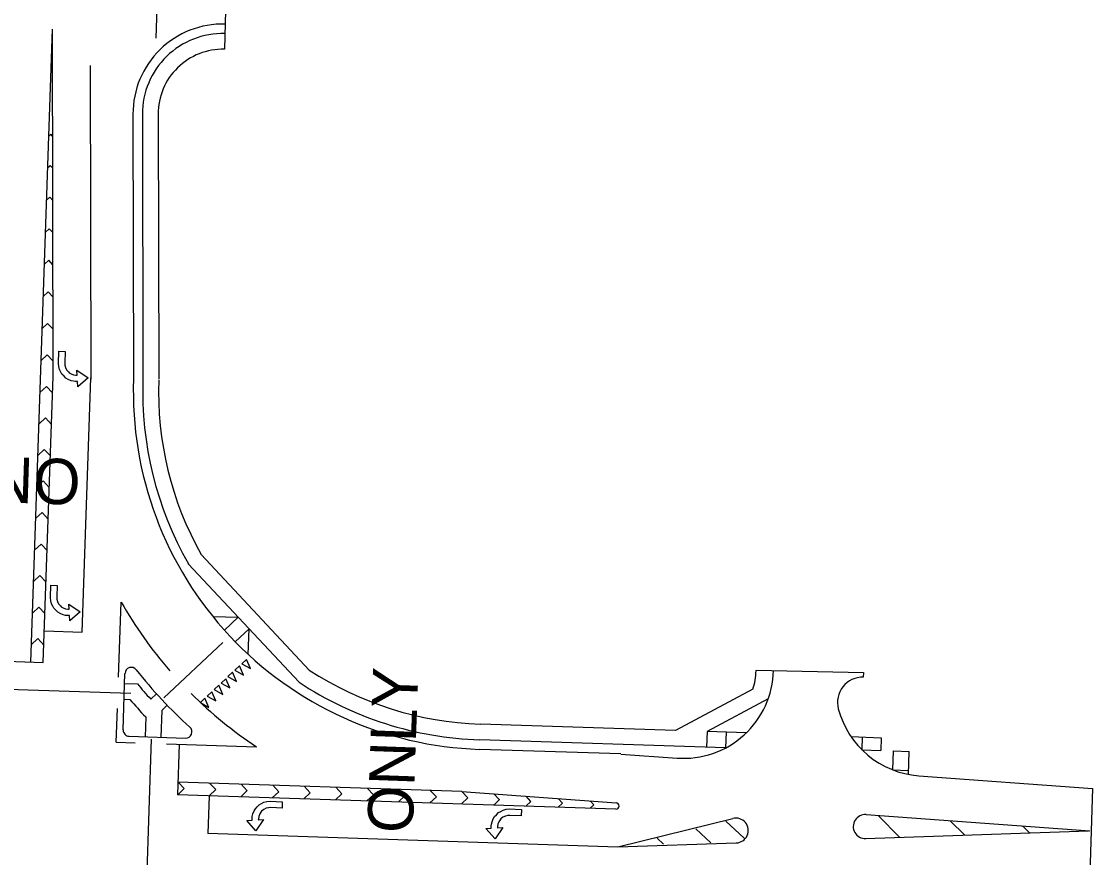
# Model space of a CAD drawing. Extents: x 979036 to 996074, y 1836928 to 1845163.
# Drawn here: x 992489.6 to 992829.2, y 1843370.6 to 1843635.7 of the extents above; entities that cross this region are included whole.
import ezdxf

# ---------------------------------------------------------------- set-up
doc = ezdxf.new("R2010")
doc.units = 0
for name, color, linetype in [('R_Proposed Road', 7, 'Continuous'), ('STRIPE_White Crosswalk', 7, 'Continuous'), ('STRIPE_White Stopbar', 7, 'Continuous'), ('STRIPE_White Turn Arrow', 7, 'Continuous'), ('STRIPE_White_6in', 7, 'Continuous'), ('STRIPE_White_ONLY', 7, 'Continuous'), ('STRIPE_White_Yield Tri', 7, 'Continuous'), ('STRIPE_Yellow Dbl 6in', 7, 'Continuous'), ('STRIPE_Yellow_45_Diag_8in', 7, 'Continuous')]:
    doc.layers.add(name, color=color, linetype=linetype)

msp = doc.modelspace()

# ---------------------------------------------------------------- linework, layer by layer
at = {"layer": 'R_Proposed Road'}
for p, q in [((992554.9, 1843665.68), (992553.93, 1843626.83)), ((992524.91, 1843606.28), (992525.09, 1843522.27)), ((992527.91, 1843606.29), (992528.09, 1843522.28)), ((992532.91, 1843606.3), (992533.09, 1843522.29)), ((992546.53, 1843466.67), (992580.81, 1843430.01)), ((992542.47, 1843463.69), (992577.56, 1843426.16)), ((992550.21, 1843447.02), (992558.31, 1843446.75)), ((992558.31, 1843446.75), (992553.93, 1843442.65)), ((992561.73, 1843443.1), (992557.34, 1843439)), ((992561.46, 1843435), (992561.73, 1843443.1)), ((992521.78, 1843411.1), (992522.39, 1843428.96)), ((992722.48, 1843430.02), (992722.47, 1843429.84)), ((992722.47, 1843430.02), (992756.51, 1843429.25)), ((992756.51, 1843429.25), (992756.47, 1843427.76)), ((992522.28, 1843425.76), (992526.33, 1843425.62)), ((992721.45, 1843423.94), (992696.95, 1843410.85)), ((992522.11, 1843420.77), (992523.95, 1843420.7)), ((992532.38, 1843422.5), (992530.54, 1843420.79)), ((992726.3, 1843420.86), (992706.95, 1843410.52)), ((992534.02, 1843417.19), (992533.74, 1843408.71)), ((992535.79, 1843418.85), (992534.02, 1843417.19)), ((992528.95, 1843415.15), (992528.75, 1843408.87)), ((992696.95, 1843410.85), (992635.06, 1843412.88)), ((992706.95, 1843410.52), (992706.78, 1843405.53)), ((992719.36, 1843410.12), (992706.95, 1843410.52)), ((992712.94, 1843410.33), (992712.78, 1843405.33)), ((992523.71, 1843409.04), (992541.57, 1843408.45)), ((992712.78, 1843405.33), (992634.89, 1843407.89)), ((992752.55, 1843408.93), (992762.14, 1843408.54)), ((992756.15, 1843408.78), (992755.98, 1843404.79)), ((992762.14, 1843408.54), (992761.98, 1843404.54)), ((992679.57, 1843403.42), (992634.8, 1843404.89)), ((992679.63, 1843403.41), (992697.42, 1843402.12)), ((992755.98, 1843404.78), (992761.98, 1843404.54)), ((992765.81, 1843398.38), (992766.01, 1843404.38)), ((992766.01, 1843404.38), (992771, 1843404.21)), ((992770.76, 1843396.96), (992771, 1843404.21)), ((992765.81, 1843398.38), (992770.81, 1843398.22)), ((992774.05, 1843396.53), (992829.16, 1843392.5)), ((992829.16, 1843392.5), (992828.27, 1843365.51))]:
    msp.add_line(p, q, dxfattribs=at)
for centre, radius, start, end in [((992553.41, 1843606.34), 28.5, 88.5687, 180.1187), ((992553.41, 1843606.34), 25.5, 88.5687, 180.1187), ((992553.41, 1843606.34), 20.5, 88.5687, 180.1187), ((992638.52, 1843518.33), 113.5, 178.0361, 268.1194), ((992638.52, 1843518.33), 110.5, 178.0361, 209.6347), ((992638.52, 1843518.33), 105.5, 178.0361, 209.3184), ((992524.39, 1843428.89), 2, 38.0831, 178.0361), ((992638.52, 1843518.33), 143, 218.0831, 228.0725), ((992638.52, 1843518.33), 105.5, 236.8372, 268.1194), ((992699.49, 1843430.54), 28.5, 265.8268, 358.7075), ((992701.98, 1843430.36), 20.5, 341.7549, 358.5567), ((992756.29, 1843419.76), 8, 88.7075, 194.6721), ((992638.54, 1843519.03), 146, 219.7747, 222.2917), ((992638.52, 1843518.33), 110.5, 236.5208, 268.1194), ((992638.54, 1843519.03), 151, 220.6303, 223.4662), ((992776.12, 1843424.95), 28.5, 194.6721, 265.8268), ((992523.78, 1843411.03), 2, 178.0361, 268.1194), ((992541.63, 1843410.45), 2, 268.1194, 48.0725)]:
    msp.add_arc(centre, radius, start, end, dxfattribs=at)
at = {"layer": 'STRIPE_White Crosswalk'}
for p, q in [((992532.3, 1843630.35), (992533.5, 1843665.48)), ((992553.39, 1843438.72), (992534.7, 1843421.25)), ((992477.09, 1843424.27), (992524.25, 1843422.65)), ((992530.65, 1843408.15), (992529.03, 1843358.83))]:
    msp.add_line(p, q, dxfattribs=at)
at = {"layer": 'STRIPE_White Stopbar'}
for p, q in [((992496.84, 1843442.44), (992508.83, 1843442.03)), ((992480.01, 1843433.01), (992496.49, 1843432.45)), ((992539.6, 1843406.51), (992539.07, 1843390.51)), ((992549.07, 1843390.19), (992548.67, 1843378.2))]:
    msp.add_line(p, q, dxfattribs=at)
at = {"layer": 'STRIPE_White Turn Arrow'}
for points in [[(992507.11, 1843525.15), (992510.73, 1843522.71), (992507.45, 1843519.84), (992507.34, 1843521.5), (992506.68, 1843521.52), (992506.1, 1843521.57), (992505.31, 1843521.76), (992504.38, 1843522.16), (992503.66, 1843522.6), (992503.08, 1843523.16), (992502.41, 1843523.81), (992502.04, 1843524.51), (992501.63, 1843525.27), (992501.39, 1843526.22), (992501.27, 1843527.21), (992501.46, 1843531.11), (992503.46, 1843531.02), (992503.32, 1843527.42), (992503.35, 1843526.73), (992503.54, 1843525.99), (992503.89, 1843525.2), (992504.44, 1843524.54), (992504.74, 1843524.31), (992505.34, 1843523.92), (992506.1, 1843523.65), (992506.83, 1843523.51), (992507.22, 1843523.49)], [(992504.57, 1843450.95), (992508.18, 1843448.51), (992504.91, 1843445.63), (992504.8, 1843447.29), (992504.13, 1843447.31), (992503.56, 1843447.37), (992502.76, 1843447.56), (992501.84, 1843447.95), (992501.12, 1843448.39), (992500.54, 1843448.96), (992499.87, 1843449.61), (992499.49, 1843450.31), (992499.08, 1843451.07), (992498.85, 1843452.02), (992498.72, 1843453), (992498.91, 1843456.9), (992500.92, 1843456.81), (992500.78, 1843453.22), (992500.8, 1843452.53), (992501, 1843451.79), (992501.35, 1843450.99), (992501.9, 1843450.34), (992502.19, 1843450.11), (992502.8, 1843449.71), (992503.55, 1843449.44), (992504.28, 1843449.31), (992504.67, 1843449.28)], [(992566.32, 1843382.63), (992563.88, 1843379.01), (992561, 1843382.29), (992562.67, 1843382.4), (992562.68, 1843383.06), (992562.74, 1843383.64), (992562.93, 1843384.43), (992563.33, 1843385.36), (992563.76, 1843386.08), (992564.33, 1843386.66), (992564.98, 1843387.33), (992565.68, 1843387.7), (992566.44, 1843388.11), (992567.39, 1843388.35), (992568.38, 1843388.47), (992572.27, 1843388.28), (992572.18, 1843386.28), (992568.59, 1843386.42), (992567.9, 1843386.39), (992567.16, 1843386.2), (992566.37, 1843385.85), (992565.71, 1843385.3), (992565.48, 1843385), (992565.09, 1843384.4), (992564.82, 1843383.65), (992564.68, 1843382.91), (992564.66, 1843382.52)], [(992642.15, 1843380.16), (992639.71, 1843376.54), (992636.83, 1843379.82), (992638.49, 1843379.92), (992638.51, 1843380.59), (992638.57, 1843381.16), (992638.76, 1843381.96), (992639.15, 1843382.89), (992639.59, 1843383.61), (992640.16, 1843384.18), (992640.81, 1843384.86), (992641.51, 1843385.23), (992642.27, 1843385.64), (992643.22, 1843385.88), (992644.2, 1843386), (992648.1, 1843385.81), (992648.01, 1843383.81), (992644.42, 1843383.95), (992643.73, 1843383.92), (992642.99, 1843383.72), (992642.2, 1843383.37), (992641.54, 1843382.82), (992641.31, 1843382.53), (992640.91, 1843381.93), (992640.64, 1843381.17), (992640.51, 1843380.44), (992640.49, 1843380.05)]]:
    msp.add_lwpolyline(points, close=True, dxfattribs=at)
at = {"layer": 'STRIPE_White_6in'}
for p, q in [((992492.5, 1843432.58), (992499.37, 1843633.16)), ((992499.6, 1843523.09), (992499.37, 1843633.16)), ((992498.22, 1843599.37), (992498.84, 1843599.96)), ((992499.44, 1843599.31), (992498.84, 1843599.96)), ((992497.87, 1843589.2), (992498.68, 1843589.96)), ((992499.47, 1843589.11), (992498.68, 1843589.96)), ((992497.52, 1843579.02), (992498.52, 1843579.96)), ((992499.49, 1843578.92), (992498.52, 1843579.96)), ((992497.17, 1843568.84), (992498.36, 1843569.96)), ((992499.51, 1843568.72), (992498.36, 1843569.96)), ((992496.82, 1843558.67), (992498.2, 1843559.95)), ((992499.53, 1843558.53), (992498.2, 1843559.95)), ((992496.47, 1843548.49), (992498.03, 1843549.95)), ((992499.55, 1843548.33), (992498.03, 1843549.95)), ((992496.12, 1843538.31), (992497.87, 1843539.95)), ((992499.57, 1843538.14), (992497.87, 1843539.95)), ((992495.77, 1843528.14), (992497.71, 1843529.95)), ((992499.59, 1843527.94), (992497.71, 1843529.95)), ((992496.49, 1843432.45), (992499.6, 1843523.09)), ((992495.43, 1843518.02), (992497.49, 1843519.96)), ((992499.42, 1843517.88), (992497.49, 1843519.96)), ((992495.08, 1843508.03), (992497.15, 1843509.96)), ((992499.08, 1843507.89), (992497.15, 1843509.96)), ((992494.74, 1843498.03), (992496.8, 1843499.97)), ((992498.74, 1843497.9), (992496.8, 1843499.97)), ((992494.4, 1843488.04), (992496.46, 1843489.97)), ((992498.4, 1843487.9), (992496.46, 1843489.97)), ((992494.05, 1843478.05), (992496.12, 1843479.98)), ((992498.05, 1843477.91), (992496.12, 1843479.98)), ((992493.71, 1843468.05), (992495.78, 1843469.98)), ((992497.71, 1843467.91), (992495.78, 1843469.98)), ((992493.37, 1843458.06), (992495.43, 1843459.99)), ((992497.37, 1843457.92), (992495.43, 1843459.99)), ((992520.35, 1843427.79), (992521.16, 1843451.6)), ((992493.03, 1843448.06), (992495.09, 1843450)), ((992497.02, 1843447.93), (992495.09, 1843450)), ((992494.75, 1843440), (992492.68, 1843438.07)), ((992494.75, 1843440), (992496.68, 1843437.93)), ((992519.64, 1843407.17), (992520.01, 1843417.8)), ((992519.64, 1843407.17), (992525.61, 1843406.97)), ((992535.6, 1843406.64), (992564.07, 1843405.71)), ((992629.16, 1843391.57), (992539.22, 1843394.52)), ((992541.15, 1843392.45), (992539.22, 1843394.52)), ((992551.14, 1843392.12), (992549.21, 1843394.19)), ((992561.16, 1843391.79), (992559.23, 1843393.86)), ((992571.15, 1843391.47), (992569.22, 1843393.53)), ((992581.15, 1843391.14), (992579.21, 1843393.21)), ((992678.03, 1843385.96), (992539.08, 1843390.52)), ((992541.15, 1843392.45), (992539.09, 1843390.52)), ((992551.15, 1843392.13), (992549.08, 1843390.19)), ((992561.16, 1843391.8), (992559.09, 1843389.86)), ((992571.15, 1843391.47), (992569.09, 1843389.54)), ((992581.15, 1843391.14), (992579.08, 1843389.21)), ((992591.14, 1843390.81), (992589.08, 1843388.88)), ((992591.14, 1843390.81), (992589.21, 1843392.88)), ((992601.14, 1843390.48), (992599.07, 1843388.55)), ((992601.13, 1843390.48), (992599.2, 1843392.55)), ((992611.13, 1843390.16), (992609.07, 1843388.22)), ((992611.13, 1843390.15), (992609.2, 1843392.22)), ((992621.13, 1843389.83), (992619.06, 1843387.89)), ((992621.12, 1843389.83), (992619.19, 1843391.89)), ((992629.16, 1843391.57), (992678.1, 1843387.96)), ((992631.12, 1843389.5), (992629.19, 1843391.56)), ((992641.11, 1843388.93), (992639.35, 1843390.82)), ((992651.09, 1843388.4), (992649.54, 1843390.06)), ((992631.12, 1843389.5), (992629.06, 1843387.57)), ((992641.11, 1843388.94), (992639.29, 1843387.23)), ((992651.1, 1843388.4), (992649.49, 1843386.9)), ((992661.08, 1843387.86), (992659.69, 1843386.56)), ((992661.08, 1843387.86), (992659.72, 1843389.31)), ((992671.07, 1843387.33), (992669.89, 1843386.23)), ((992671.07, 1843387.33), (992669.92, 1843388.56))]:
    msp.add_line(p, q, dxfattribs=at)
for centre, radius, start, end in [((992638.52, 1843518.33), 135, 209.6224, 220.9884), ((992638.52, 1843518.33), 135, 225.1748, 236.5331), ((992678.03, 1843386.96), 1, 268.1194, 85.7831)]:
    msp.add_arc(centre, radius, start, end, dxfattribs=at)
at = {"layer": 'STRIPE_White_Yield Tri'}
for p, q in [((992558.7, 1843431.36), (992557.24, 1843430)), ((992559.97, 1843428.45), (992558.7, 1843431.36)), ((992560.89, 1843433.41), (992559.43, 1843432.05)), ((992559.43, 1843432.05), (992562.16, 1843430.5)), ((992562.16, 1843430.5), (992560.89, 1843433.41)), ((992554.31, 1843427.27), (992552.85, 1843425.9)), ((992555.58, 1843424.35), (992554.31, 1843427.27)), ((992556.5, 1843429.32), (992555.04, 1843427.95)), ((992555.04, 1843427.95), (992557.77, 1843426.4)), ((992557.77, 1843426.4), (992556.5, 1843429.32)), ((992557.24, 1843430), (992559.97, 1843428.45)), ((992552.12, 1843425.22), (992550.66, 1843423.85)), ((992550.66, 1843423.85), (992553.39, 1843422.3)), ((992553.39, 1843422.3), (992552.12, 1843425.22)), ((992552.85, 1843425.9), (992555.58, 1843424.35)), ((992547.74, 1843421.12), (992546.28, 1843419.75)), ((992549.01, 1843418.2), (992547.74, 1843421.12)), ((992549.93, 1843423.17), (992548.47, 1843421.8)), ((992548.47, 1843421.8), (992551.2, 1843420.25)), ((992551.2, 1843420.25), (992549.93, 1843423.17)), ((992546.28, 1843419.75), (992549.01, 1843418.2))]:
    msp.add_line(p, q, dxfattribs=at)
at = {"layer": 'STRIPE_Yellow Dbl 6in'}
for p, q in [((992511.38, 1843621.72), (992511.59, 1843522.24)), ((992508.83, 1843442.03), (992511.59, 1843522.68)), ((992678.6, 1843373.96), (992715.12, 1843382.97)), ((992757.38, 1843384.21), (992828.24, 1843379.04)), ((992678.64, 1843373.93), (992548.67, 1843378.2)), ((992757.2, 1843376.62), (992827.92, 1843379.01)), ((992678.6, 1843373.96), (992716.19, 1843375.23))]:
    msp.add_line(p, q, dxfattribs=at)
for centre, radius, start, end in [((992716.06, 1843379.16), 3.93, 271.9369, 103.866), ((992757.1, 1843380.4), 3.82, 85.8268, 271.9335)]:
    msp.add_arc(centre, radius, start, end, dxfattribs=at)
at = {"layer": 'STRIPE_Yellow_45_Diag_8in'}
for p, q in [((992768.09, 1843376.99), (992761.15, 1843383.93)), ((992703.36, 1843379.73), (992708.13, 1843375.29)), ((992712.91, 1843382.09), (992718.69, 1843376.71)), ((992788.61, 1843377.68), (992784.03, 1843382.26)), ((992809.13, 1843378.37), (992806.92, 1843380.59)), ((992691.08, 1843376.7), (992693.13, 1843374.78))]:
    msp.add_line(p, q, dxfattribs=at)

# ---------------------------------------------------------------- texts
at = {"layer": 'STRIPE_White_ONLY'}
for rotation, p in [(178.1709, (992508.54, 1843496.78)), (87.9663, (992613.58, 1843378.17))]:
    msp.add_text('ONLY', height=14.4, rotation=rotation, dxfattribs=at).set_placement(p)

doc.saveas('drawing.dxf')
